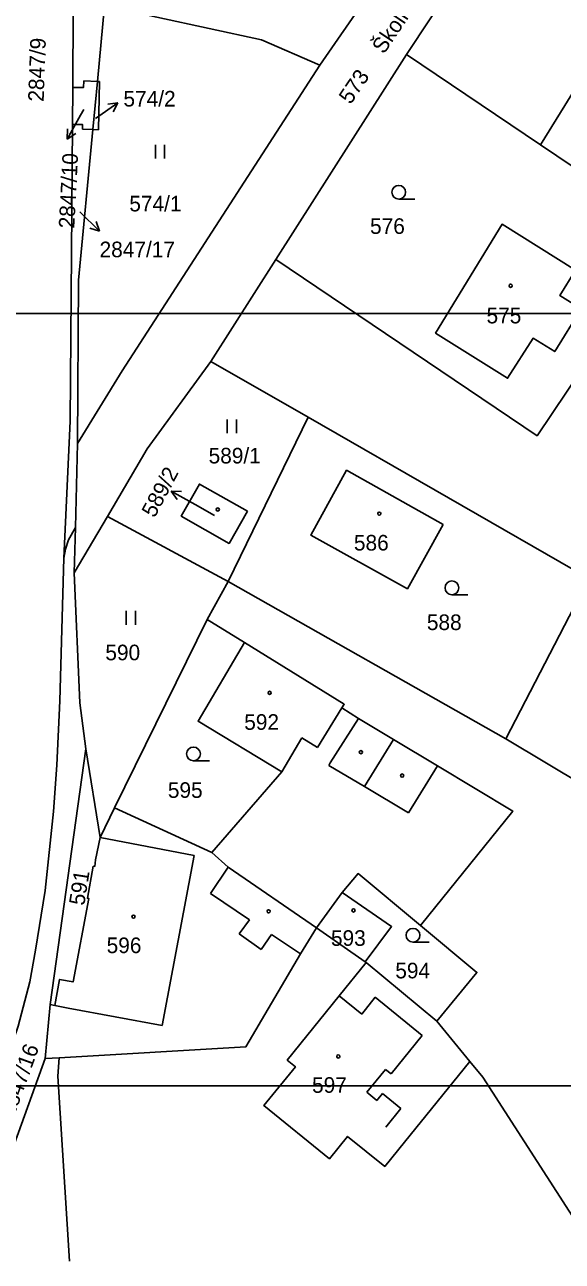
# Model space of a CAD drawing. Extents: x -558500 to -557517, y -1073973 to -1073051.
# Drawn here: x -558184.7 to -558126.2, y -1073803.2 to -1073668.6 of the extents above; entities that cross this region are included whole.
import ezdxf

# ---------------------------------------------------------------- set-up
doc = ezdxf.new("R2010")
doc.units = 0
for name, color, linetype in [('Default', 7, 'Continuous'), ('Hranice parcel', 7, 'Continuous'), ('Parcelní čísla', 7, 'Continuous'), ('Pop  PČ popisy', 7, 'Continuous'), ('Vnitřní kresba', 7, 'Continuous'), ('Vrstva 1', 7, 'Continuous'), ('Značky budov', 7, 'Continuous'), ('Značky kultur', 7, 'Continuous')]:
    doc.layers.add(name, color=color, linetype=linetype)

msp = doc.modelspace()

# ---------------------------------------------------------------- linework, layer by layer
at = {"layer": 'Default'}
msp.add_lwpolyline([(-557909.21, -1073700), (-558500, -1073700), (-558500, -1073200), (-557800, -1073200), (-557800, -1073567.6)], dxfattribs=at)
at = {"layer": 'Hranice parcel'}
for p, q in [((-558126.57, -1073635.37), (-558152.59, -1073672.96)), ((-558176.83, -1073674.75), (-558176.05, -1073666.5)), ((-558157.39, -1073694.14), (-558143.16, -1073671.79)), ((-558128.54, -1073681.64), (-558143.16, -1073671.79)), ((-558179.54, -1073679.43), (-558179.49, -1073675.4)), ((-558178.3, -1073674.68), (-558176.83, -1073674.75)), ((-558176.83, -1073674.75), (-558177.33, -1073679.98)), ((-558176.83, -1073674.75), (-558176.6, -1073674.76)), ((-558176.6, -1073674.76), (-558176.71, -1073680)), ((-558178.45, -1073679.93), (-558177.33, -1073679.98)), ((-558176.71, -1073680), (-558177.33, -1073679.98)), ((-558114.13, -1073691.34), (-558128.54, -1073681.64)), ((-558164.46, -1073705.23), (-558157.39, -1073694.14)), ((-558153.86, -1073711.3), (-558164.46, -1073705.23)), ((-558153.86, -1073711.3), (-558162.58, -1073729.18)), ((-558123.29, -1073728.86), (-558153.86, -1073711.3)), ((-558178.98, -1073714.16), (-558179.23, -1073723.31)), ((-558179.37, -1073728.25), (-558175.74, -1073722.09)), ((-558162.58, -1073729.18), (-558175.74, -1073722.09)), ((-558179.23, -1073723.31), (-558179.37, -1073728.25)), ((-558162.58, -1073729.18), (-558164.87, -1073733.32)), ((-558132.34, -1073746.32), (-558162.58, -1073729.18)), ((-558123.29, -1073728.86), (-558132.34, -1073746.32)), ((-558174.95, -1073753.84), (-558164.87, -1073733.32)), ((-558164.87, -1073733.32), (-558160.79, -1073735.84)), ((-558178.08, -1073747.39), (-558181.97, -1073775.25)), ((-558178.08, -1073747.39), (-558176.52, -1073757.07)), ((-558176.52, -1073757.07), (-558174.95, -1073753.84)), ((-558174.95, -1073753.84), (-558164.36, -1073758.7)), ((-558152.96, -1073766.88), (-558150.14, -1073763.05)), ((-558152.96, -1073766.88), (-558147.64, -1073770.59)), ((-558147.64, -1073770.59), (-558147.54, -1073770.67)), ((-558147.54, -1073770.67), (-558139.85, -1073777.06)), ((-558181.97, -1073775.25), (-558182.51, -1073781.13)), ((-558139.85, -1073777.06), (-558136.25, -1073781.43)), ((-558182.51, -1073781.13), (-558187.36, -1073794.52)), ((-558182.51, -1073781.13), (-558181.01, -1073781.05))]:
    msp.add_line(p, q, dxfattribs=at)
for points in [[(-558086.19, -1073392.25), (-558100.56, -1073410.01), (-558117.51, -1073431.08), (-558131.78, -1073449.27), (-558138.48, -1073457.68), (-558143.38, -1073464.02), (-558146.99, -1073468.89), (-558150.46, -1073473.83), (-558152.02, -1073476.41), (-558154.26, -1073480.97), (-558156.46, -1073486.6), (-558158.91, -1073494.31), (-558160.3, -1073500.48), (-558162.16, -1073510.4), (-558165.76, -1073536.46), (-558169.94, -1073565.43), (-558173.74, -1073591.61), (-558177.66, -1073620.33), (-558178.51, -1073631.87), (-558179.02, -1073643), (-558179.24, -1073655.12), (-558179.45, -1073666.94), (-558179.49, -1073675.4)], [(-558143.16, -1073671.79), (-558122.68, -1073640.91), (-558116.74, -1073631.82), (-558110.18, -1073623.69)], [(-558128.54, -1073681.64), (-558110.84, -1073652.98), (-558090.78, -1073665.45)], [(-558176.05, -1073666.5), (-558158.95, -1073670.2), (-558152.59, -1073672.96)], [(-558152.59, -1073672.96), (-558174.12, -1073706.25), (-558178.98, -1073714.16)], [(-558179.49, -1073675.4), (-558178.35, -1073675.4), (-558178.3, -1073674.68)], [(-558180.47, -1073726.64), (-558179.79, -1073711.73), (-558179.61, -1073688.81), (-558179.54, -1073679.43)], [(-558179.54, -1073679.43), (-558178.44, -1073679.44), (-558178.45, -1073679.93)], [(-558177.33, -1073679.98), (-558178.88, -1073696.38), (-558178.98, -1073714.16)], [(-558157.39, -1073694.14), (-558128.92, -1073713.32), (-558114.13, -1073691.34)], [(-558124.75, -1073695.3), (-558132.74, -1073690.28), (-558139.98, -1073702.13), (-558132.13, -1073707.05), (-558129.35, -1073702.69), (-558127, -1073704.15), (-558124.1, -1073699.49), (-558126.45, -1073698.03), (-558124.75, -1073695.3)], [(-558175.74, -1073722.09), (-558171.39, -1073714.72), (-558164.46, -1073705.23)], [(-558139.17, -1073722.99), (-558149.67, -1073717.07), (-558153.56, -1073724.14), (-558143.05, -1073729.97), (-558139.17, -1073722.99)], [(-558160.49, -1073721.53), (-558165.71, -1073718.57), (-558167.69, -1073722.06), (-558162.47, -1073725.03), (-558160.49, -1073721.53)], [(-558179.23, -1073723.31), (-558179.97, -1073724.66), (-558180.29, -1073725.65), (-558180.47, -1073726.64)], [(-558189.49, -1073787.81), (-558187.05, -1073782.29), (-558185.46, -1073777.61), (-558184.2, -1073772.75), (-558183.57, -1073769.31), (-558182.51, -1073762.81), (-558181.61, -1073754.21), (-558181.25, -1073749.17), (-558180.93, -1073742.19), (-558180.47, -1073726.64)], [(-558179.37, -1073728.25), (-558178.74, -1073742.4), (-558178.08, -1073747.39)], [(-558160.79, -1073735.84), (-558165.86, -1073744.39), (-558156.72, -1073749.9), (-558164.36, -1073758.7)], [(-558160.79, -1073735.84), (-558149.94, -1073742.55), (-558150.18, -1073742.93), (-558148.38, -1073744.09), (-558144.55, -1073746.39), (-558139.78, -1073749.25), (-558131.58, -1073754.18), (-558141.63, -1073766.63)], [(-558108.92, -1073736.57), (-558119.39, -1073754.05), (-558132.34, -1073746.32)], [(-558181.97, -1073775.25), (-558181.48, -1073775.34), (-558180.95, -1073772.5), (-558179.48, -1073772.78), (-558177.77, -1073763.68), (-558177.92, -1073763.66), (-558177.27, -1073760.18), (-558177.12, -1073760.21), (-558177.05, -1073759.47), (-558176.52, -1073757.07)], [(-558164.36, -1073758.7), (-558162.58, -1073760.28), (-558152.96, -1073766.88)], [(-558150.14, -1073763.05), (-558148.43, -1073760.98), (-558141.63, -1073766.63)], [(-558147.64, -1073770.59), (-558144.77, -1073766.75), (-558150.14, -1073763.05)], [(-558181.01, -1073781.05), (-558160.65, -1073779.83), (-558154.69, -1073769.71), (-558152.96, -1073766.88)], [(-558141.63, -1073766.63), (-558135.48, -1073771.74), (-558139.85, -1073777.06)], [(-558147.54, -1073770.67), (-558150.48, -1073774.29), (-558156.15, -1073781.28), (-558155.26, -1073782.01), (-558158.69, -1073786.24), (-558151.55, -1073792.03), (-558149.56, -1073789.59), (-558145.52, -1073792.86), (-558143.38, -1073790.22), (-558136.25, -1073781.43)], [(-558179.85, -1073803.19), (-558181.12, -1073783.05), (-558181.01, -1073781.05)], [(-558136.25, -1073781.43), (-558134.84, -1073783.14), (-558124.36, -1073799.37)]]:
    msp.add_lwpolyline(points, dxfattribs=at)
at = {"layer": 'Pop  PČ popisy'}
for p, q in [((-558178.32, -1073677.78), (-558178.66, -1073678.4)), ((-558177.05, -1073678.78), (-558174.59, -1073677.06)), ((-558174.59, -1073677.06), (-558175.7, -1073677.22)), ((-558174.59, -1073677.06), (-558175.12, -1073678.04)), ((-558178.66, -1073678.4), (-558180.11, -1073681.02)), ((-558180.11, -1073681.02), (-558180.07, -1073679.91)), ((-558180.11, -1073681.02), (-558179.19, -1073680.39)), ((-558178.75, -1073688.95), (-558176.59, -1073691.03)), ((-558176.59, -1073691.03), (-558176.96, -1073689.98)), ((-558176.59, -1073691.03), (-558177.66, -1073690.7)), ((-558166.16, -1073720.8), (-558168.79, -1073719.34)), ((-558168.79, -1073719.34), (-558167.67, -1073719.39)), ((-558168.79, -1073719.34), (-558168.15, -1073720.27)), ((-558164.05, -1073721.99), (-558166.16, -1073720.8))]:
    msp.add_line(p, q, dxfattribs=at)
at = {"layer": 'Vnitřní kresba'}
for p, q in [((-558152.86, -1073747.27), (-558150.18, -1073742.93)), ((-558151.46, -1073748.94), (-558148.38, -1073744.09)), ((-558156.72, -1073749.9), (-558154.56, -1073746.22)), ((-558154.56, -1073746.22), (-558152.86, -1073747.27)), ((-558147.74, -1073751.5), (-558144.55, -1073746.39)), ((-558151.61, -1073749.2), (-558151.46, -1073748.94)), ((-558151.61, -1073749.2), (-558147.74, -1073751.5)), ((-558142.92, -1073754.36), (-558139.78, -1073749.25)), ((-558147.74, -1073751.5), (-558142.92, -1073754.36)), ((-558176.52, -1073757.07), (-558166.27, -1073759.01)), ((-558169.76, -1073777.52), (-558166.27, -1073759.01)), ((-558164.5, -1073763.14), (-558162.58, -1073760.28)), ((-558164.5, -1073763.14), (-558160.25, -1073766.01)), ((-558161.38, -1073767.55), (-558160.25, -1073766.01)), ((-558161.38, -1073767.55), (-558158.98, -1073769.26)), ((-558158.98, -1073769.26), (-558157.87, -1073767.62)), ((-558157.87, -1073767.62), (-558154.69, -1073769.71)), ((-558150.48, -1073774.29), (-558148.03, -1073776.28)), ((-558148.03, -1073776.28), (-558146.55, -1073774.45)), ((-558146.55, -1073774.45), (-558141.43, -1073778.61)), ((-558181.48, -1073775.34), (-558180, -1073775.65)), ((-558180, -1073775.65), (-558169.76, -1073777.52)), ((-558144.83, -1073782.8), (-558141.43, -1073778.61)), ((-558147.47, -1073784.78), (-558145.45, -1073782.3)), ((-558145.45, -1073782.3), (-558144.83, -1073782.8)), ((-558147.47, -1073784.78), (-558146.38, -1073785.67)), ((-558146.38, -1073785.67), (-558145.78, -1073784.93)), ((-558145.78, -1073784.93), (-558143.76, -1073786.57)), ((-558145.4, -1073788.59), (-558143.76, -1073786.57))]:
    msp.add_line(p, q, dxfattribs=at)
at = {"layer": 'Vrstva 1'}
msp.add_line((-557516.53, -1073784.09), (-558357.53, -1073784.09), dxfattribs=at)
at = {"layer": 'Značky budov'}
for centre in [(-558131.8, -1073696.98), (-558163.71, -1073721.34), (-558146.11, -1073721.79), (-558158.06, -1073741.3), (-558148.12, -1073747.76), (-558143.62, -1073750.31), (-558172.89, -1073765.67), (-558158.17, -1073765.09), (-558148.92, -1073764.99), (-558150.58, -1073780.89)]:
    msp.add_circle(centre, 0.175, dxfattribs=at)
at = {"layer": 'Značky kultur'}
for p, q in [((-558170.5, -1073683.13), (-558170.5, -1073681.63)), ((-558169.5, -1073683.13), (-558169.5, -1073681.63)), ((-558144, -1073687.55), (-558142.25, -1073687.55)), ((-558162.67, -1073713.05), (-558162.67, -1073711.55)), ((-558161.67, -1073713.05), (-558161.67, -1073711.55)), ((-558138.2, -1073730.62), (-558136.45, -1073730.62)), ((-558173.68, -1073733.89), (-558173.68, -1073732.39)), ((-558172.68, -1073733.89), (-558172.68, -1073732.39)), ((-558166.36, -1073748.71), (-558164.61, -1073748.71)), ((-558142.44, -1073768.45), (-558140.69, -1073768.45))]:
    msp.add_line(p, q, dxfattribs=at)
for centre in [(-558144, -1073686.8), (-558138.2, -1073729.87), (-558166.36, -1073747.96), (-558142.44, -1073767.7)]:
    msp.add_circle(centre, 0.75, dxfattribs=at)

# ---------------------------------------------------------------- texts
at = {"layer": 'Parcelní čísla'}
for s, rotation, p in [('2847/9', 88, (-558182.68, -1073676.97)), ('573', 56, (-558149.24, -1073677.32)), ('2847/10', 87, (-558179.35, -1073690.79)), ('589/2', 62, (-558170.6, -1073722.33)), ('591', 81, (-558178.26, -1073764.52)), ('2847/16', 70, (-558185.97, -1073787.64))]:
    msp.add_text(s, height=1.7, rotation=rotation, dxfattribs=at).set_placement(p)
for s, p in [('574/2', (-558173.99, -1073677.47)), ('574/1', (-558173.35, -1073688.89)), ('576', (-558147.12, -1073691.34)), ('2847/17', (-558176.59, -1073693.88)), ('575', (-558134.43, -1073701.08)), ('589/1', (-558164.71, -1073716.33)), ('586', (-558148.88, -1073725.81)), ('588', (-558140.93, -1073734.47)), ('590', (-558175.96, -1073737.76)), ('592', (-558160.83, -1073745.33)), ('595', (-558169.15, -1073752.74)), ('596', (-558175.82, -1073769.64)), ('593', (-558151.38, -1073768.85)), ('594', (-558144.37, -1073772.39)), ('597', (-558153.44, -1073784.85))]:
    msp.add_text(s, height=1.7, dxfattribs=at).set_placement(p)
at = {"layer": 'Pop  PČ popisy'}
msp.add_text('Školní', height=1.7, rotation=56, dxfattribs=at).set_placement((-558145.62, -1073671.85))

doc.saveas('drawing.dxf')
